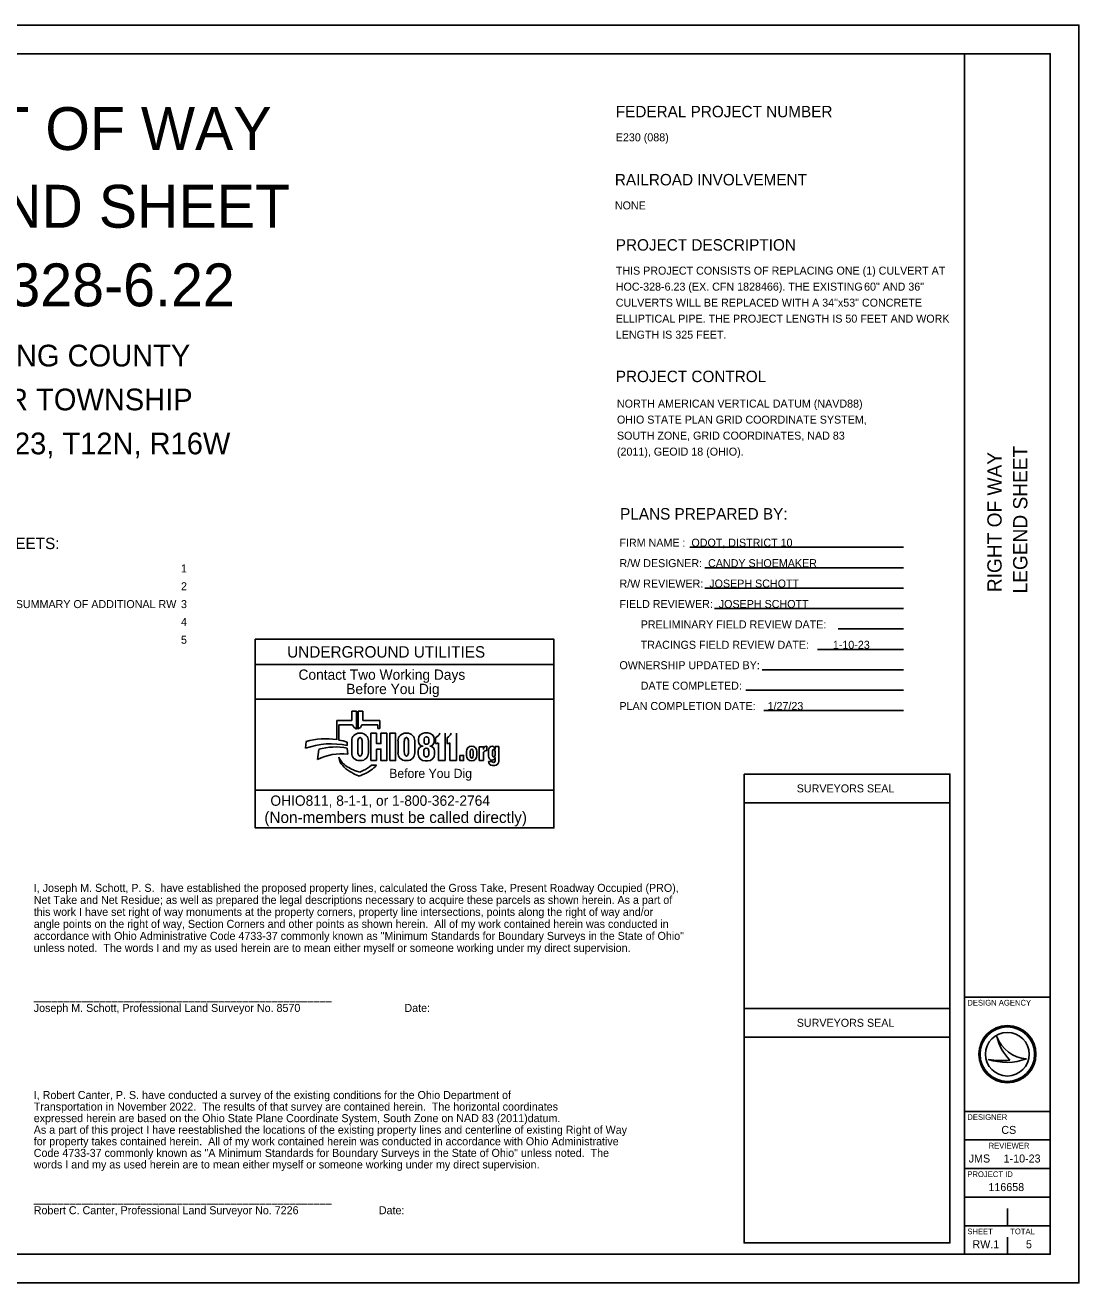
# Model space of a CAD drawing. Extents: x 0 to 34, y 0 to 22.
# Drawn here: x 15.57 to 34, y 0 to 22 of the extents above; entities that cross this region are included whole.
import ezdxf

# ---------------------------------------------------------------- set-up
doc = ezdxf.new("R2010")
doc.units = 0
for name, color, linetype in [('SH_Border', 7, 'Continuous'), ('SH_Cut_Line', 7, 'Continuous'), ('SH_Data', 7, 'Continuous'), ('SH_Text', 7, 'Continuous')]:
    doc.layers.add(name, color=color, linetype=linetype)

msp = doc.modelspace()

# ---------------------------------------------------------------- linework, layer by layer
at = {"layer": 'SH_Border'}
for p, q in [((32, 0.5), (32, 21.5)), ((32, 5), (33.5, 5)), ((32, 3), (33.5, 3)), ((32, 2.5), (33.5, 2.5)), ((32, 2), (33.5, 2)), ((32, 1.5), (33.5, 1.5)), ((32, 1), (33.5, 1))]:
    msp.add_line(p, q, dxfattribs=at)
msp.add_lwpolyline([(1.5, 21.5), (33.5, 21.5), (33.5, 0.5), (1.5, 0.5)], close=True, dxfattribs=at)
at = {"layer": 'SH_Cut_Line'}
msp.add_lwpolyline([(0, 0), (34, 0), (34, 22), (0, 22)], close=True, dxfattribs=at)
at = {"layer": 'SH_Data'}
for p, q in [((21.365, 10.002), (21.285, 10.002)), ((21.285, 10.002), (21.285, 9.836)), ((21.365, 9.685), (21.365, 10.002)), ((21.476, 10.002), (21.396, 10.002)), ((21.396, 10.002), (21.396, 9.685)), ((21.476, 9.836), (21.476, 10.002)), ((21.285, 9.836), (21.022, 9.836)), ((21.022, 9.836), (21.022, 9.501)), ((21.059, 9.495), (21.059, 9.759)), ((21.059, 9.759), (21.3, 9.759)), ((21.46, 9.759), (21.739, 9.759)), ((21.774, 9.836), (21.476, 9.836)), ((21.739, 9.759), (21.739, 9.695)), ((21.739, 9.695), (21.774, 9.695)), ((21.774, 9.695), (21.774, 9.836)), ((20.487, 9.467), (20.473, 9.35)), ((21.283, 9.481), (21.283, 9.269)), ((21.392, 9.286), (21.392, 9.468)), ((21.441, 9.614), (21.417, 9.614)), ((21.466, 9.468), (21.466, 9.286)), ((21.575, 9.269), (21.575, 9.481)), ((21.719, 9.613), (21.618, 9.613)), ((21.618, 9.613), (21.618, 9.135)), ((22.094, 9.481), (22.094, 9.269)), ((22.203, 9.286), (22.203, 9.468)), ((22.252, 9.614), (22.227, 9.614)), ((22.277, 9.468), (22.277, 9.286)), ((22.386, 9.269), (22.386, 9.481)), ((22.45, 9.507), (22.45, 9.471)), ((22.549, 9.454), (22.549, 9.512)), ((22.613, 9.621), (22.564, 9.621)), ((22.63, 9.512), (22.63, 9.454)), ((22.727, 9.471), (22.727, 9.507)), ((22.75, 9.433), (22.75, 9.534)), ((22.917, 9.613), (22.917, 9.135)), ((22.95, 9.433), (22.95, 9.534)), ((23.117, 9.613), (23.117, 9.135)), ((20.707, 9.332), (20.685, 9.152)), ((21.206, 9.399), (21.206, 9.457)), ((21.216, 9.249), (21.206, 9.355)), ((21.719, 9.135), (21.719, 9.337)), ((22.445, 9.301), (22.445, 9.25)), ((22.546, 9.241), (22.546, 9.302)), ((22.631, 9.302), (22.631, 9.241)), ((22.733, 9.25), (22.733, 9.301)), ((22.799, 9.135), (22.799, 9.447)), ((22.999, 9.135), (22.999, 9.447)), ((23.291, 9.226), (23.291, 9.294)), ((23.358, 9.225), (23.358, 9.294)), ((23.406, 9.294), (23.406, 9.225)), ((23.473, 9.294), (23.473, 9.226)), ((23.586, 9.378), (23.513, 9.378)), ((23.513, 9.378), (23.513, 9.135)), ((23.586, 9.331), (23.586, 9.378)), ((23.586, 9.135), (23.586, 9.262)), ((23.635, 9.312), (23.647, 9.312)), ((23.647, 9.386), (23.641, 9.386)), ((23.647, 9.312), (23.647, 9.386)), ((23.675, 9.213), (23.675, 9.317)), ((23.747, 9.227), (23.747, 9.303)), ((23.79, 9.333), (23.79, 9.38)), ((23.79, 9.38), (23.855, 9.38)), ((23.79, 9.303), (23.79, 9.227)), ((23.855, 9.38), (23.855, 9.121)), ((21.058, 9.195), (21.063, 9.168)), ((21.417, 9.135), (21.441, 9.135)), ((21.618, 9.135), (21.719, 9.135)), ((21.717, 9.055), (21.631, 9.055)), ((21.714, 9.052), (21.717, 9.055)), ((22.227, 9.135), (22.252, 9.135)), ((22.566, 9.129), (22.612, 9.129)), ((22.917, 9.135), (22.799, 9.135)), ((23.117, 9.135), (22.999, 9.135)), ((23.513, 9.135), (23.586, 9.135)), ((23.675, 9.121), (23.747, 9.121)), ((23.785, 9.052), (23.745, 9.052)), ((23.79, 9.121), (23.79, 9.191)), ((21.423, 8.934), (21.335, 8.965)), ((21.359, 8.888), (21.414, 8.864)), ((21.414, 8.864), (21.509, 8.905)), ((21.485, 8.961), (21.423, 8.934)), ((28.146, 8.399), (31.746, 8.399)), ((24.821, 7.957), (19.596, 7.957)), ((28.146, 4.299), (31.746, 4.299)), ((32.567, 4.31), (32.567, 4.31)), ((32.75, 4), (32.75, 4)), ((32.417, 3.91), (32.417, 3.91)), ((33.087, 3.919), (33.087, 3.919)), ((32.75, 1), (32.75, 1.3)), ((32.375, 0.675), (32.375, 0.675)), ((32.75, 0.5), (32.75, 0.8))]:
    msp.add_line(p, q, dxfattribs=at)
for points in [[(19.596, 11.257), (24.821, 11.257), (24.821, 10.817), (19.596, 10.817)], [(19.596, 10.817), (24.821, 10.817), (24.821, 10.212), (19.596, 10.212)], [(19.596, 10.212), (24.821, 10.212), (24.821, 8.617), (19.596, 8.617)], [(23.175, 9.225), (23.241, 9.225), (23.241, 9.135), (23.175, 9.135)], [(28.146, 8.899), (31.746, 8.899), (31.746, 4.799), (28.146, 4.799)], [(19.596, 8.617), (24.821, 8.617), (24.821, 7.957), (19.596, 7.957)], [(28.146, 4.799), (31.746, 4.799), (31.746, 0.699), (28.146, 0.699)]]:
    msp.add_lwpolyline(points, close=True, dxfattribs=at)
for points in [[(21.719, 9.337), (21.795, 9.337), (21.795, 9.135), (21.897, 9.135), (21.897, 9.613), (21.795, 9.613), (21.795, 9.433), (21.719, 9.433), (21.719, 9.613)], [(21.948, 9.135), (22.05, 9.135), (22.05, 9.613), (21.948, 9.613), (21.948, 9.135)], [(22.531, 9.387), (22.531, 9.387)], [(22.647, 9.387), (22.647, 9.387)]]:
    msp.add_lwpolyline(points, dxfattribs=at)
for radius in [0.5, 0.477, 0.477, 0.382]:
    msp.add_circle((32.75, 4), radius, dxfattribs=at)
for centre, radius, start, end in [((21.437, 9.814), 0.147, 201.9296, 240.7469), ((21.324, 9.814), 0.147, 299.2531, 338.0704), ((20.83, 8.293), 1.224, 81.0007, 106.3144), ((20.83, 8.293), 1.224, 72.1402, 79.2074), ((21.417, 9.481), 0.134, 90, 180), ((21.441, 9.481), 0.134, 0, 90), ((22.227, 9.481), 0.134, 90, 180), ((22.252, 9.481), 0.134, 0, 90), ((22.564, 9.507), 0.114, 90, 180), ((22.534, 9.471), 0.0837, 180, 268.1442), ((22.613, 9.507), 0.114, 0, 90), ((22.644, 9.471), 0.0837, 272.2058, 0), ((22.7, 9.657), 0.132, 292.5572, 340.7355), ((22.9, 9.657), 0.132, 292.5572, 340.7355), ((20.925, 8.097), 1.332, 77.8238, 109.8274), ((21.113, 8.305), 0.95, 83.8248, 116.8021), ((21.006, 8.28), 1.094, 79.44, 105.8467), ((21.417, 9.269), 0.134, 180, 270), ((21.441, 9.269), 0.134, 270, 0), ((22.227, 9.269), 0.134, 180, 270), ((22.252, 9.269), 0.134, 270, 0), ((22.531, 9.301), 0.0865, 90, 180), ((22.566, 9.25), 0.121, 180, 270), ((22.612, 9.25), 0.121, 270, 0), ((22.647, 9.301), 0.0865, 0, 90), ((22.738, 9.564), 0.132, 275.1733, 297.0931), ((22.938, 9.564), 0.132, 275.1733, 297.0931), ((23.386, 9.294), 0.0956, 92.5886, 180), ((23.378, 9.294), 0.0956, 0, 87.4114), ((23.641, 9.331), 0.0548, 90, 180), ((23.635, 9.262), 0.0493, 90, 180), ((23.743, 9.317), 0.0686, 92.6865, 180), ((23.737, 9.333), 0.0524, 0, 86.9262), ((21.338, 9.303), 0.3, 201.0457, 232.5314), ((21.274, 9.204), 0.214, 189.6817, 216.0884), ((21.474, 9.35), 0.461, 216.0884, 235.7167), ((21.626, 9.678), 0.773, 232.5314, 241.794), ((21.27, 9.454), 0.538, 293.4582, 312.0712), ((21.27, 9.454), 0.599, 293.4582, 317.8286), ((23.386, 9.226), 0.0956, 180, 267.4114), ((23.378, 9.226), 0.0956, 272.5886, 0), ((23.744, 9.213), 0.0692, 180, 265.7132), ((23.745, 9.121), 0.0699, 180, 270), ((23.743, 9.191), 0.0467, 264.7825, 0), ((23.785, 9.121), 0.0699, 270, 0), ((21.722, 9.715), 0.903, 235.7167, 246.2325), ((21.499, 9.441), 0.504, 241.794, 250.9821), ((33.116, 4.498), 0.58, 198.9257, 198.9319), ((33.347, 4.47), 0.796, 191.6379, 191.6421), ((33.116, 4.498), 0.58, 198.9319, 267.1657), ((33.347, 4.47), 0.796, 191.6421, 226.0947), ((32.739, 4.87), 1.013, 251.4576, 290.0832), ((32.648, 5.154), 1.266, 259.4964, 259.4995), ((32.739, 4.87), 1.013, 251.4527, 251.4576), ((32.648, 5.154), 1.266, 259.4995, 276.6672)]:
    msp.add_arc(centre, radius, start, end, dxfattribs=at)
for centre, major_axis, ratio, start_param, end_param in [((21.429, 9.468), (0, 0.0723), 0.514403, 4.712389, 7.853982), ((22.24, 9.468), (0, 0.0723), 0.514403, 4.712389, 7.853982), ((22.59, 9.512), (0.0404, 0), 0.969373, 0, 3.141593), ((21.429, 9.286), (0, 0.0723), 0.514403, 1.570796, 4.712389), ((22.24, 9.286), (0, 0.0723), 0.514403, 1.570796, 4.712389), ((22.588, 9.302), (0, 0.0535), 0.794529, 4.712389, 7.853982), ((22.588, 9.241), (0.0425, 0), 0.959837, 3.141593, 6.283185), ((22.59, 9.454), (0.0404, 0), 0.818453, 3.141593, 6.283185), ((23.382, 9.294), (0, 0.0434), 0.553236, 4.712389, 7.853982), ((23.768, 9.303), (0, 0.0275), 0.777179, 4.712389, 7.853982), ((23.382, 9.225), (0, 0.046), 0.522014, 1.570796, 4.712389), ((23.768, 9.227), (0, 0.0275), 0.777179, 1.570796, 4.712389), ((23.768, 9.121), (0.0214, 0), 0.959012, 3.141593, 6.283185)]:
    msp.add_ellipse(centre, major_axis=major_axis, ratio=ratio, start_param=start_param, end_param=end_param, dxfattribs=at)
at = {"layer": 'SH_Text'}
for p, q in [((27.198, 12.867), (30.935, 12.867)), ((27.462, 12.51), (30.935, 12.51)), ((27.462, 12.152), (30.935, 12.152)), ((27.627, 11.795), (30.935, 11.795)), ((29.79, 11.438), (30.935, 11.438)), ((29.432, 11.081), (30.935, 11.081)), ((28.463, 10.724), (30.935, 10.724)), ((28.177, 10.366), (30.935, 10.366)), ((28.492, 10.01), (30.935, 10.01))]:
    msp.add_line(p, q, dxfattribs=at)

# ---------------------------------------------------------------- texts
at = {"layer": 'SH_Data'}
for s, height, p in [('RIGHT OF WAY', 0.75, (12.527, 19.816)), ('LEGEND SHEET', 0.75, (12.458, 18.457)), ('HOC-328-6.22', 0.75, (12.716, 17.082)), ('HOCKING COUNTY', 0.38, (13.802, 16.03)), ('STARR TOWNSHIP', 0.38, (13.9, 15.262)), ('SECTION 23, T12N, R16W', 0.38, (12.977, 14.493)), ('INDEX OF SHEETS:', 0.2, (13.692, 12.835)), ('     1', 0.14, (18.038, 12.427)), ('     2', 0.14, (18.038, 12.115)), ('PROPERTY MAP & SUMMARY OF ADDITIONAL RW', 0.14, (13.692, 11.803)), ('     3', 0.14, (18.038, 11.803)), ('     4', 0.14, (18.038, 11.491)), ('     5', 0.14, (18.038, 11.179)), ('UNDERGROUND UTILITIES', 0.2, (20.155, 10.937)), ('Contact Two Working Days', 0.18, (20.353, 10.549)), ('Before You Dig', 0.18, (21.188, 10.299)), ('Before You Dig', 0.15972, (21.939, 8.832)), ('SURVEYORS SEAL', 0.14, (29.067, 8.579)), ('OHIO811, 8-1-1, or 1-800-362-2764', 0.18, (19.862, 8.345)), ('(Non-members must be called directly)', 0.2, (19.756, 8.044)), ('DESIGN AGENCY', 0.1, (32.05, 4.85)), ('SURVEYORS SEAL', 0.14, (29.067, 4.479)), ('DESIGNER', 0.1, (32.05, 2.85)), ('CS', 0.14, (32.645, 2.605)), ('REVIEWER', 0.1, (32.422, 2.35)), ('JMS', 0.14, (32.074, 2.105)), ('1-10-23', 0.14, (32.685, 2.105)), ('PROJECT ID', 0.1, (32.05, 1.85)), ('116658', 0.14, (32.419, 1.605)), ('SHEET', 0.1, (32.05, 0.85)), ('TOTAL', 0.1, (32.8, 0.85)), ('RW.1', 0.14, (32.14, 0.605)), ('5', 0.14, (33.076, 0.605))]:
    msp.add_text(s, height=height, dxfattribs=at).set_placement(p)
for s, p in [('RIGHT OF WAY', (32.65, 12.082)), ('LEGEND SHEET', (33.1, 12.06))]:
    msp.add_text(s, height=0.25, rotation=90, dxfattribs=at).set_placement(p)
at = {"layer": 'SH_Text'}
for s, height, p in [('FEDERAL PROJECT NUMBER', 0.2, (25.902, 20.388)), ('E230 (088)', 0.14, (25.902, 19.968)), ('RAILROAD INVOLVEMENT', 0.2, (25.886, 19.197)), ('NONE', 0.14, (25.886, 18.777)), ('PROJECT DESCRIPTION', 0.2, (25.902, 18.056)), ('THIS PROJECT CONSISTS OF REPLACING ONE (1) CULVERT AT ', 0.14, (25.902, 17.636)), ('HOC-328-6.23 (EX. CFN 1828466). THE EXISTING', 0.14, (25.902, 17.356)), (' 60" AND 36" ', 0.14, (30.192, 17.356)), ('CULVERTS WILL BE REPLACED WITH A 34"x53" CONCRETE ', 0.14, (25.902, 17.076)), ('ELLIPTICAL PIPE. THE PROJECT LENGTH IS 50 FEET AND WORK ', 0.14, (25.902, 16.796)), ('LENGTH IS 325 FEET.', 0.14, (25.902, 16.516)), ('PROJECT CONTROL', 0.2, (25.902, 15.756)), ('NORTH AMERICAN VERTICAL DATUM (NAVD88)', 0.14, (25.922, 15.31)), ('OHIO STATE PLAN GRID COORDINATE SYSTEM,', 0.14, (25.922, 15.03)), ('SOUTH ZONE, GRID COORDINATES, NAD 83', 0.14, (25.922, 14.75)), ('(2011), GEOID 18 (OHIO).', 0.14, (25.922, 14.47)), ('PLANS PREPARED BY:', 0.2, (25.978, 13.352)), ('FIRM NAME :  ODOT, DISTRICT 10', 0.14, (25.966, 12.877)), ('R/W DESIGNER:  CANDY SHOEMAKER', 0.14, (25.966, 12.519)), ('R/W REVIEWER:  JOSEPH SCHOTT', 0.14, (25.966, 12.162)), ('FIELD REVIEWER:  JOSEPH SCHOTT', 0.14, (25.966, 11.805)), ('PRELIMINARY FIELD REVIEW DATE:', 0.14, (26.338, 11.448)), ('TRACINGS FIELD REVIEW DATE:        1-10-23', 0.14, (26.338, 11.091)), ('OWNERSHIP UPDATED BY:', 0.14, (25.966, 10.734)), ('DATE COMPLETED:', 0.14, (26.338, 10.376)), ('PLAN COMPLETION DATE:    1/27/23', 0.14, (25.966, 10.02)), ('I, Joseph M. Schott, P. S.  have established the proposed property lines, calculated the Gross Take, Present Roadway Occupied (PRO),', 0.14, (15.723, 6.839)), ('Net Take and Net Residue; as well as prepared the legal descriptions necessary to acquire these parcels as shown herein. As a part of', 0.14, (15.723, 6.629)), ('this work I have set right of way monuments at the property corners, property line intersections, points along the right of way and/or', 0.14, (15.723, 6.419)), ('angle points on the right of way, Section Corners and other points as shown herein.  All of my work contained herein was conducted in', 0.14, (15.723, 6.209)), ('accordance with Ohio Administrative Code 4733-37 commonly known as "Minimum Standards for Boundary Surveys in the State of Ohio"', 0.14, (15.723, 5.999)), ('unless noted.  The words I and my as used herein are to mean either myself or someone working under my direct supervision.', 0.14, (15.723, 5.789)), ('__________________________________________________', 0.14, (15.723, 4.949)), ('Joseph M. Schott, Professional Land Surveyor No. 8570                                   Date:                                     ', 0.14, (15.723, 4.739)), ('I, Robert Canter, P. S. have conducted a survey of the existing conditions for the Ohio Department of', 0.14, (15.723, 3.216)), ('Transportation in November 2022.  The results of that survey are contained herein.  The horizontal coordinates', 0.14, (15.723, 3.013)), ('expressed herein are based on the Ohio State Plane Coordinate System, South Zone on NAD 83 (2011)datum.', 0.14, (15.723, 2.811)), ('As a part of this project I have reestablished the locations of the existing property lines and centerline of existing Right of Way ', 0.14, (15.723, 2.608)), ('for property takes contained herein.  All of my work contained herein was conducted in accordance with Ohio Administrative ', 0.14, (15.723, 2.406)), ('Code 4733-37 commonly known as "A Minimum Standards for Boundary Surveys in the State of Ohio" unless noted.  The ', 0.14, (15.723, 2.203)), ('words I and my as used herein are to mean either myself or someone working under my direct supervision.', 0.14, (15.723, 2.001)), ('__________________________________________________', 0.14, (15.723, 1.41)), ('Robert C. Canter, Professional Land Surveyor No. 7226                           Date:                ', 0.14, (15.723, 1.2))]:
    msp.add_text(s, height=height, dxfattribs=at).set_placement(p)

doc.saveas('drawing.dxf')
